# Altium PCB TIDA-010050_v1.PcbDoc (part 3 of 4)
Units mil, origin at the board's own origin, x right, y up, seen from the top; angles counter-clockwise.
Board outline 2060.77 x 1300 mil, 4 copper layers (Top Layer, signal1, signal2, Bottom Layer), stack 23.6 mil thick; 58 components, 30 nets, 158 pads, 41 vias.
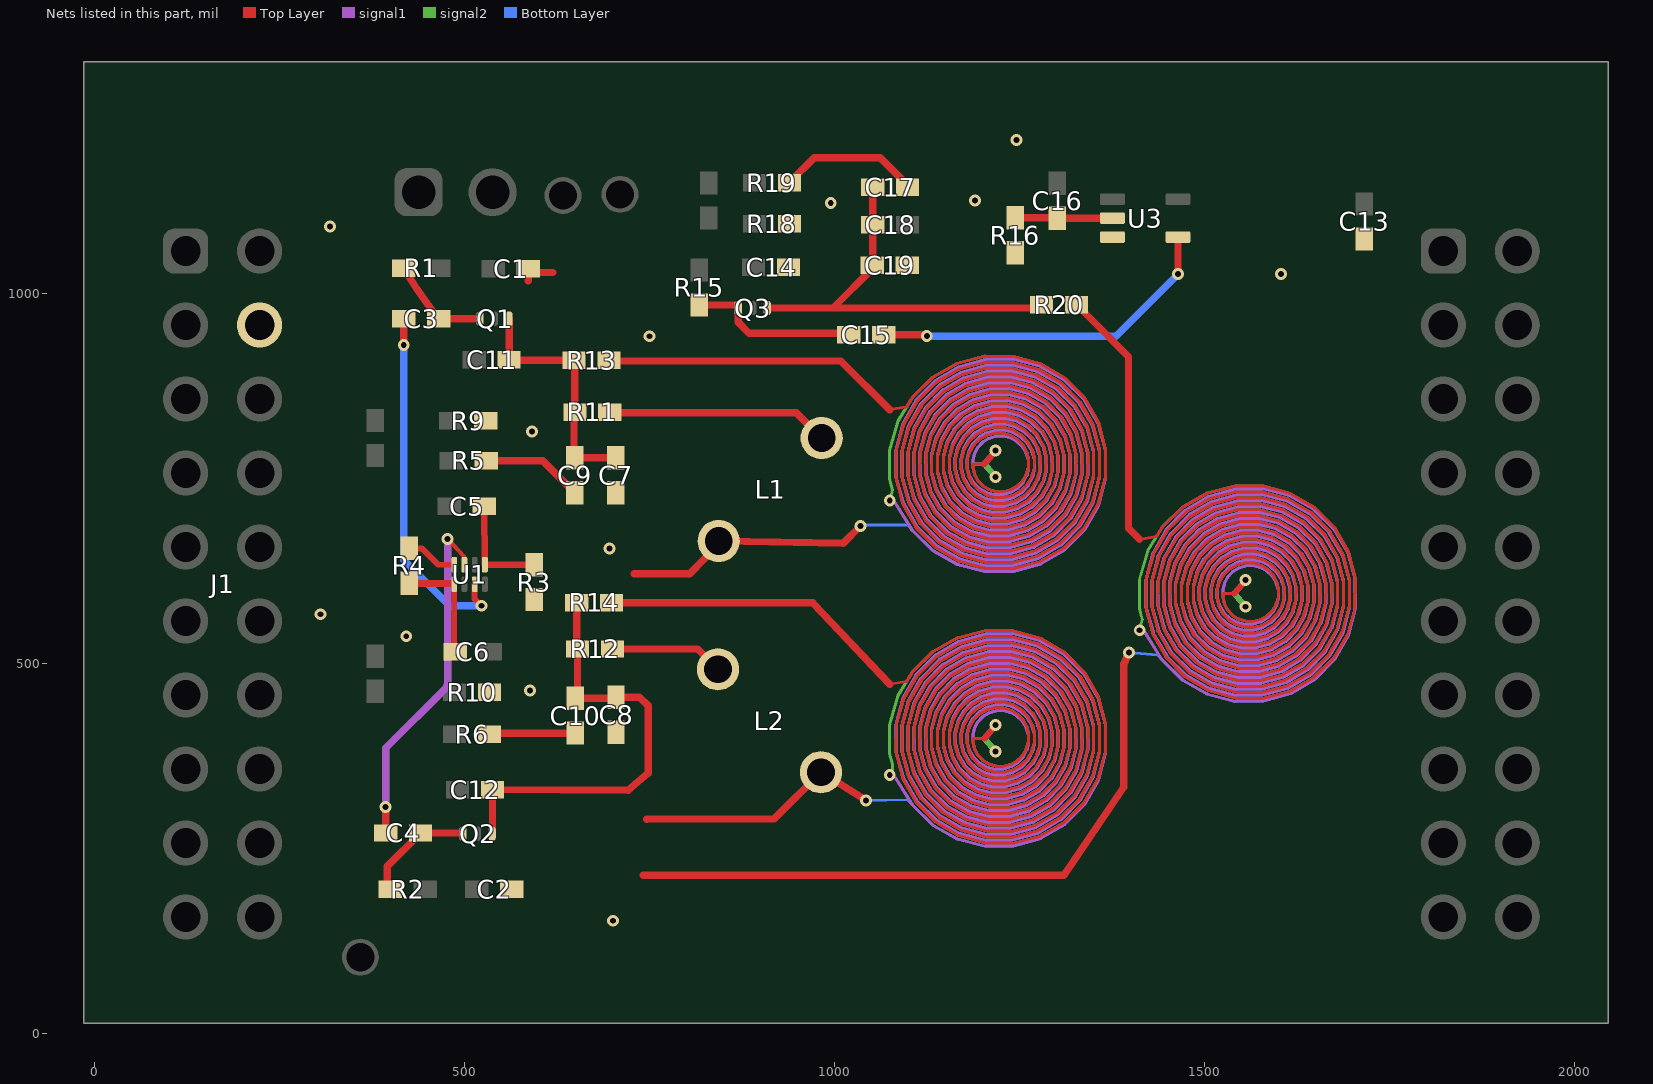
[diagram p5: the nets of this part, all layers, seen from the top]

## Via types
v1: diameter 16, hole 8, Top Layer to Bottom Layer, 40 vias
v2: diameter 16/16/16/16 (per signal layer), hole 8, Top Layer to Bottom Layer, 1 vias

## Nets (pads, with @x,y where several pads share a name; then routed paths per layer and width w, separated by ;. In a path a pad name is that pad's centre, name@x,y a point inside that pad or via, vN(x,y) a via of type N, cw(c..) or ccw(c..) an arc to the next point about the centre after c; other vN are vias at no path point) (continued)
GND: (continued)
  Bottom Layer w4: v1@1035.99,686.52 1098.94,686.52 1105.24,679.29 1132.74,652.26 1166.23,633.31 1203.39,623.7 1241.69,624.03 1278.51,634.24 1311.36,653.59 1338.02,680.72 1356.71,713.76 1366.19,750.41 1365.85,788.18 1355.78,824.5 1336.69,856.89 1309.93,883.18 1277.36,901.6 1241.21,910.94 1203.96,910.61 1168.16,900.67 1136.22,881.85 1110.3,855.46 1092.15,823.34 1082.94,787.7 1083.27,750.98 1093.08,715.69 1111.64,684.2 1137.65,658.66 1169.31,640.77 1204.45,631.7 1240.64,632.03 1275.43,641.7 1306.45,660 1331.62,685.64 1349.25,716.84 1358.19,751.47 1357.85,787.13 1348.32,821.41 1330.29,851.98 1305.02,876.78 1274.27,894.15 1240.16,902.94 1205.02,902.61 1171.24,893.22 1141.13,875.45 1116.71,850.55 1099.6,820.25 1090.94,786.65 1091.27,752.04 1100.53,718.77 1118.04,689.12 1142.56,665.06 1172.4,648.22 1205.5,639.7 1239.58,640.03 1272.34,649.15 1301.54,666.4 1325.22,690.55 1341.8,719.93 1350.19,752.52 1349.85,786.08 1340.87,818.32 1323.89,847.07 1300.11,870.38 1271.18,886.69 1239.1,894.94 1206.07,894.61 1174.33,885.76 1146.04,869.04 1123.11,845.64 1107.05,817.17 1098.94,785.6 1099.27,753.09 1107.99,721.86 1124.44,694.03 1147.48,671.46 1175.49,655.68 1206.55,647.7 1238.53,648.03 1269.25,656.61 1296.63,672.8 1318.82,695.46 1334.34,723.02 1342.19,753.57 1341.85,785.03 1333.41,815.24 1317.49,842.16 1295.19,863.98 1268.09,879.24 1238.05,886.94 1207.12,886.61 1177.42,878.31 1150.96,862.64 1129.51,840.72 1114.51,814.08 1106.94,784.54 1107.27,754.14 1115.44,724.95 1130.84,698.94 1152.39,677.87 1178.58,663.13 1207.6,655.7 1237.48,656.03 1266.16,664.06 1291.72,679.2 1312.42,700.37 1326.89,726.11 1334.19,754.63 1333.85,783.97 1325.96,812.15 1311.08,837.24 1290.28,857.57 1265.01,871.78 1237,878.94 1208.18,878.61 1180.51,870.85 1155.87,856.24 1135.91,835.81 1121.96,810.99 1114.94,783.49 1115.27,755.2 1122.9,728.04 1137.24,703.85 1157.3,684.27 1181.67,670.59 1208.66,663.7 1236.43,664.03 1263.08,671.52 1286.8,685.6 1306.02,705.29 1319.44,729.2 1326.19,755.68 1325.85,782.92 1318.5,809.06 1304.68,832.33 1285.37,851.17 1261.92,864.33 1235.94,870.94 1209.23,870.61 1183.6,863.4 1160.78,849.84 1142.31,830.9 1129.42,807.9 1122.94,782.44 1123.27,756.25 1130.35,731.12 1143.65,708.76 1162.21,690.67 1184.75,678.04 1209.71,671.7 1235.37,672.03 1259.99,678.97 1281.89,692 1299.61,710.2 1311.98,732.28 1318.19,756.73 1317.85,781.87 1311.05,805.97 1298.28,827.42 1280.46,844.77 1258.83,856.87 1234.89,862.94 1210.28,862.61 1186.68,855.94 1165.69,843.44 1148.71,825.99 1136.87,804.81 1130.94,781.38 1131.27,757.3 1137.81,734.21 1150.05,713.68 1167.12,697.07 1187.84,685.49 1210.76,679.7 1234.32,680.03 1256.9,686.43 1276.98,698.4 1293.21,715.11 1304.53,735.37 1310.19,757.78 1309.85,780.81 1303.59,802.88 1291.88,822.51 1275.55,838.37 1255.74,849.42 1233.84,854.94 1211.34,854.61 1189.77,848.49 1170.6,837.04 1155.12,821.08 1144.33,801.73 1138.94,780.33 1139.27,758.36 1145.26,737.3 1156.45,718.59 1172.04,703.47 1190.93,692.95 1211.82,687.7 1233.27,688.03 1253.81,693.88 1272.07,704.81 1286.81,720.02 1297.07,738.46 1302.19,758.84 1301.85,779.76 1296.14,799.8 1285.48,817.6 1270.63,831.97 1252.65,841.96 1232.78,846.94 1212.39,846.61 1192.86,841.03 1175.52,830.63 1161.52,816.16 1151.78,798.64 1146.94,779.28 1147.27,759.41 1152.72,740.39 1162.85,723.5 1176.95,709.87 1194.02,700.4 1212.87,695.7 1232.21,696.03 1250.72,701.34 1267.15,711.21 1280.41,724.93 1289.62,741.55 1294.19,759.89 1293.85,778.71 1288.68,796.71 1279.08,812.68 1265.72,825.57 1249.57,834.51 1231.73,838.94 1213.44,838.61 1195.95,833.58 1180.43,824.23 1167.92,811.25 1159.24,795.55 1154.94,778.22 1155.27,760.46 1160.17,743.48 1169.25,728.41 1181.86,716.28 1197.11,707.86 1213.92,703.7 1231.16,704.03 1247.64,708.79 1262.24,717.61 1274.01,729.85 1282.16,744.63 1286.19,760.94 1285.85,777.65 1281.23,793.62 1272.67,807.77 1260.81,819.16 1246.48,827.05 1230.68,830.94 1214.49,830.61 1199.04,826.12 1185.34,817.83 1174.32,806.34 1166.69,792.46 1162.94,777.17 1163.27,761.51 1167.63,746.56 1175.65,733.33 1186.77,722.68 1200.19,715.31 1214.98,711.7 1230.11,712.03 1244.55,716.25 1257.33,724.01 1267.61,734.76 1274.71,747.72 1278.19,762 1277.85,776.6 1273.77,790.53 1266.27,802.86 1255.9,812.76 1243.39,819.6 1229.62,822.94 1215.55,822.61 1202.12,818.67 1190.25,811.43 1180.72,801.43 1174.15,789.37 1170.94,776.12 1171.27,762.57 1175.08,749.65 1182.06,738.24 1191.69,729.08 1203.28,722.77 1216.03,719.7 1229.05,720.03 1241.46,723.7 1252.42,730.41 1261.2,739.67 1267.25,750.81 1270.19,763.05 1269.85,775.55 1266.32,787.45 1259.87,797.95 1250.99,806.36 1240.3,812.14 1228.57,814.94 1216.6,814.61 1205.21,811.21 1195.16,805.03 1187.12,796.51 1181.6,786.29 1178.94,775.06 1179.27,763.62 1182.53,752.74 1188.46,743.15 1196.6,735.48 1206.37,730.22 1217.08,727.7 1228,728.03 1238.37,731.16 1247.51,736.81 1254.8,744.58 1259.8,753.9 1262.19,764.1 1261.85,774.49 1258.86,784.36 1253.47,793.04 1246.07,799.96 1237.21,804.69 1227.52,806.94 1217.65,806.61 1208.3,803.76 1200.08,798.63 1193.52,791.6 1189.06,783.2 1186.94,774.01 1187.27,769.32 1202.52,769.32 ; v1(1042.51,314.54) 1098.94,315.41 1105.24,308.18 1132.74,281.15 1166.23,262.2 1203.4,252.59 1241.69,252.92 1278.52,263.13 1311.37,282.48 1338.03,309.61 1356.71,342.64 1366.19,379.3 1365.86,417.07 1355.78,453.39 1336.69,485.78 1309.93,512.07 1277.36,530.49 1241.21,539.83 1203.97,539.5 1168.16,529.56 1136.22,510.73 1110.31,484.35 1092.15,452.23 1082.94,416.59 1083.28,379.87 1093.08,344.57 1111.64,313.09 1137.66,287.55 1169.32,269.65 1204.45,260.59 1240.64,260.92 1275.43,270.59 1306.46,288.88 1331.63,314.52 1349.26,345.73 1358.19,380.35 1357.86,416.02 1348.33,450.3 1330.29,480.87 1305.02,505.67 1274.27,523.04 1240.16,531.83 1205.02,531.5 1171.25,522.1 1141.13,504.33 1116.71,479.44 1099.6,449.14 1090.94,415.54 1091.28,380.92 1100.54,347.66 1118.04,318 1142.57,293.95 1172.41,277.11 1205.5,268.59 1239.59,268.92 1272.34,278.04 1301.54,295.28 1325.22,319.44 1341.8,348.82 1350.19,381.41 1349.86,414.97 1340.87,447.21 1323.89,475.96 1300.11,499.26 1271.18,515.58 1239.11,523.83 1206.07,523.5 1174.34,514.65 1146.05,497.93 1123.11,474.52 1107.06,446.05 1098.94,414.48 1099.28,381.98 1107.99,350.75 1124.44,322.92 1147.48,300.35 1175.49,284.56 1206.56,276.59 1238.54,276.92 1269.25,285.49 1296.63,301.69 1318.82,324.35 1334.35,351.91 1342.19,382.46 1341.86,413.91 1333.42,444.12 1317.49,471.04 1295.2,492.86 1268.1,508.13 1238.05,515.83 1207.13,515.5 1177.42,507.19 1150.96,491.53 1129.51,469.61 1114.51,442.97 1106.94,413.43 1107.28,383.03 1115.44,353.84 1130.85,327.83 1152.39,306.75 1178.58,292.02 1207.61,284.59 1237.48,284.92 1266.17,292.95 1291.72,308.09 1312.42,329.26 1326.89,354.99 1334.19,383.51 1333.86,412.86 1325.96,441.04 1311.09,466.13 1290.29,486.46 1265.01,500.67 1237,507.83 1208.18,507.5 1180.51,499.74 1155.87,485.13 1135.91,464.7 1121.97,439.88 1114.94,412.38 1115.28,384.08 1122.9,356.92 1137.25,332.74 1157.3,313.16 1181.67,299.47 1208.66,292.59 1236.43,292.92 1263.08,300.4 1286.81,314.49 1306.02,334.17 1319.44,358.08 1326.19,384.57 1325.86,411.81 1318.51,437.95 1304.69,461.22 1285.37,480.06 1261.92,493.22 1235.95,499.83 1209.23,499.5 1183.6,492.28 1160.78,478.73 1142.32,459.79 1129.42,436.79 1122.94,411.32 1123.28,385.14 1130.35,360.01 1143.65,337.65 1162.22,319.56 1184.76,306.93 1209.71,300.59 1235.38,300.92 1259.99,307.86 1281.89,320.89 1299.62,339.09 1311.98,361.17 1318.19,385.62 1317.86,410.75 1311.05,434.86 1298.28,456.31 1280.46,473.66 1258.83,485.76 1234.89,491.83 1210.29,491.5 1186.69,484.83 1165.7,472.32 1148.72,454.88 1136.88,433.7 1130.94,410.27 1131.28,386.19 1137.81,363.1 1150.05,342.56 1167.13,325.96 1187.85,314.38 1210.77,308.59 1234.32,308.92 1256.9,315.31 1276.98,327.29 1293.22,344 1304.53,364.26 1310.19,386.67 1309.86,409.7 1303.6,431.77 1291.88,451.4 1275.55,467.26 1255.74,478.31 1233.84,483.83 1211.34,483.5 1189.78,477.37 1170.61,465.92 1155.12,449.96 1144.33,430.61 1138.94,409.22 1139.28,387.24 1145.26,366.19 1156.45,347.48 1172.04,332.36 1190.93,321.84 1211.82,316.59 1233.27,316.92 1253.81,322.77 1272.07,333.69 1286.81,348.91 1297.07,367.35 1302.19,387.73 1301.86,408.65 1296.14,428.68 1285.48,446.48 1270.64,460.86 1252.66,470.85 1232.79,475.83 1212.39,475.5 1192.86,469.92 1175.52,459.52 1161.52,445.05 1151.79,427.53 1146.94,408.16 1147.28,388.3 1152.72,369.28 1162.85,352.39 1176.95,338.76 1194.02,329.29 1212.87,324.59 1232.22,324.92 1250.73,330.22 1267.16,340.1 1280.41,353.82 1289.62,370.43 1294.19,388.78 1293.86,407.59 1288.69,425.6 1279.08,441.57 1265.73,454.45 1249.57,463.4 1231.73,467.83 1213.44,467.5 1195.95,462.46 1180.43,453.12 1167.92,440.14 1159.24,424.44 1154.94,407.11 1155.28,389.35 1160.17,372.36 1169.26,357.3 1181.86,345.16 1197.11,336.75 1213.93,332.59 1231.16,332.92 1247.64,337.68 1262.25,346.5 1274.01,358.73 1282.16,373.52 1286.19,389.83 1285.86,406.54 1281.23,422.51 1272.68,436.66 1260.81,448.05 1246.48,455.94 1230.68,459.83 1214.5,459.5 1199.04,455.01 1185.34,446.72 1174.32,435.23 1166.7,421.35 1162.94,406.06 1163.28,390.4 1167.63,375.45 1175.66,362.21 1186.78,351.57 1200.2,344.2 1214.98,340.59 1230.11,340.92 1244.55,345.13 1257.33,352.9 1267.61,363.65 1274.71,376.61 1278.19,390.89 1277.86,405.49 1273.78,419.42 1266.28,431.75 1255.9,441.65 1243.39,448.49 1229.63,451.83 1215.55,451.5 1202.13,447.56 1190.26,440.32 1180.72,430.31 1174.15,418.26 1170.94,405 1171.28,391.46 1175.08,378.54 1182.06,367.12 1191.69,357.97 1203.28,351.66 1216.03,348.59 1229.06,348.92 1241.46,352.59 1252.42,359.3 1261.21,368.56 1267.25,379.7 1270.19,391.94 1269.86,404.43 1266.32,416.33 1259.87,426.84 1250.99,435.25 1240.31,441.03 1228.57,443.83 1216.6,443.5 1205.21,440.1 1195.17,433.92 1187.13,425.4 1181.61,415.17 1178.94,403.95 1179.28,392.51 1182.54,381.63 1188.46,372.04 1196.6,364.37 1206.37,359.11 1217.09,356.59 1228,356.92 1238.38,360.04 1247.51,365.7 1254.81,373.47 1259.8,382.79 1262.19,392.99 1261.86,403.38 1258.87,413.24 1253.47,421.92 1246.08,428.85 1237.22,433.58 1227.52,435.83 1217.66,435.5 1208.3,432.65 1200.08,427.51 1193.53,420.49 1189.06,412.09 1186.94,402.9 1187.28,398.21 1202.53,398.21 ; v1(1397.9,514.36) 1436.74,511.26 1443.03,504.03 1470.53,477 1504.02,458.05 1541.19,448.44 1579.49,448.77 1616.31,458.98 1649.16,478.33 1675.82,505.47 1694.5,538.5 1703.98,575.15 1703.65,612.93 1693.57,649.24 1674.48,681.63 1647.73,707.92 1615.15,726.34 1579,735.68 1541.76,735.35 1505.95,725.41 1474.01,706.59 1448.1,680.2 1429.94,648.08 1420.74,612.44 1421.07,575.72 1430.87,540.43 1449.43,508.95 1475.45,483.4 1507.11,465.51 1542.24,456.44 1578.43,456.77 1613.22,466.44 1644.25,484.74 1669.42,510.38 1687.05,541.58 1695.98,576.21 1695.65,611.87 1686.12,646.15 1668.08,676.72 1642.81,701.52 1612.06,718.89 1577.95,727.68 1542.81,727.35 1509.04,717.96 1478.93,700.19 1454.5,675.29 1437.39,644.99 1428.74,611.39 1429.07,576.78 1438.33,543.51 1455.83,513.86 1480.36,489.8 1510.2,472.96 1543.29,464.44 1577.38,464.77 1610.13,473.89 1639.33,491.14 1663.02,515.29 1679.59,544.67 1687.98,577.26 1687.65,610.82 1678.66,643.07 1661.68,671.81 1637.9,695.12 1608.98,711.43 1576.9,719.68 1543.86,719.35 1512.13,710.5 1483.84,693.78 1460.9,670.38 1444.85,641.91 1436.74,610.34 1437.07,577.83 1445.78,546.6 1462.24,518.77 1485.27,496.21 1513.28,480.42 1544.35,472.44 1576.33,472.77 1607.05,481.35 1634.42,497.54 1656.61,520.2 1672.14,547.76 1679.98,578.31 1679.65,609.77 1671.21,639.98 1655.28,666.9 1632.99,688.72 1605.89,703.98 1575.84,711.68 1544.92,711.35 1515.21,703.05 1488.75,687.38 1467.3,665.47 1452.3,638.82 1444.74,609.28 1445.07,578.88 1453.24,549.69 1468.64,523.68 1490.18,502.61 1516.37,487.87 1545.4,480.44 1575.27,480.77 1603.96,488.8 1629.51,503.94 1650.21,525.11 1664.68,550.85 1671.98,579.37 1671.65,608.71 1663.75,636.89 1648.88,661.99 1628.08,682.32 1602.8,696.52 1574.79,703.68 1545.97,703.35 1518.3,695.59 1493.66,680.98 1473.71,660.55 1459.76,635.73 1452.74,608.23 1453.07,579.94 1460.69,552.78 1475.04,528.59 1495.09,509.01 1519.46,495.33 1546.45,488.44 1574.22,488.77 1600.87,496.26 1624.6,510.34 1643.81,530.03 1657.23,553.94 1663.98,580.42 1663.65,607.66 1656.3,633.8 1642.48,657.07 1623.17,675.91 1599.71,689.07 1573.74,695.68 1547.02,695.35 1521.39,688.14 1498.57,674.58 1480.11,655.64 1467.21,632.64 1460.74,607.18 1461.07,580.99 1468.15,555.87 1481.44,533.51 1500.01,515.41 1522.55,502.78 1547.51,496.44 1573.17,496.77 1597.78,503.71 1619.69,516.74 1637.41,534.94 1649.78,557.02 1655.98,581.47 1655.65,606.61 1648.84,630.71 1636.08,652.16 1618.25,669.51 1596.62,681.61 1572.68,687.68 1548.08,687.35 1524.48,680.68 1503.49,668.18 1486.51,650.73 1474.67,629.56 1468.74,606.12 1469.07,582.04 1475.6,558.95 1487.84,538.42 1504.92,521.81 1525.64,510.24 1548.56,504.44 1572.11,504.77 1594.69,511.17 1614.77,523.15 1631.01,539.85 1642.32,560.11 1647.98,582.53 1647.65,605.55 1641.39,627.63 1629.67,647.25 1613.34,663.11 1593.54,674.16 1571.63,679.68 1549.13,679.35 1527.57,673.23 1508.4,661.78 1492.91,645.82 1482.12,626.47 1476.74,605.07 1477.07,583.1 1483.06,562.04 1494.24,543.33 1509.83,528.21 1528.72,517.69 1549.61,512.44 1571.06,512.77 1591.61,518.62 1609.86,529.55 1624.61,544.76 1634.87,563.2 1639.98,583.58 1639.65,604.5 1633.93,624.54 1623.27,642.34 1608.43,656.71 1590.45,666.71 1570.58,671.68 1550.18,671.35 1530.65,665.77 1513.31,655.38 1499.31,640.9 1489.58,623.38 1484.74,604.02 1485.07,584.15 1490.51,565.13 1500.65,548.24 1514.74,534.62 1531.81,525.15 1550.67,520.44 1570.01,520.77 1588.52,526.08 1604.95,535.95 1618.2,549.68 1627.41,566.29 1631.98,584.63 1631.65,603.45 1626.48,621.45 1616.87,637.43 1603.52,650.31 1587.36,659.25 1569.52,663.68 1551.24,663.35 1533.74,658.32 1518.22,648.97 1505.71,635.99 1497.03,620.29 1492.74,602.96 1493.07,585.2 1497.97,568.22 1507.05,553.15 1519.66,541.02 1534.9,532.6 1551.72,528.44 1568.95,528.77 1585.43,533.53 1600.04,542.35 1611.8,554.59 1619.96,569.38 1623.98,585.69 1623.65,602.39 1619.02,618.36 1610.47,632.51 1598.6,643.91 1584.27,651.8 1568.47,655.68 1552.29,655.35 1536.83,650.86 1523.14,642.57 1512.11,631.08 1504.49,617.2 1500.74,601.91 1501.07,586.26 1505.42,571.31 1513.45,558.07 1524.57,547.42 1537.99,540.06 1552.77,536.44 1567.9,536.77 1582.34,540.99 1595.13,548.75 1605.4,559.5 1612.5,572.46 1615.98,586.74 1615.65,601.34 1611.57,615.27 1604.07,627.6 1593.69,637.5 1581.18,644.34 1567.42,647.68 1553.34,647.35 1539.92,643.41 1528.05,636.17 1518.52,626.17 1511.94,614.12 1508.74,600.86 1509.07,587.31 1512.87,574.39 1519.85,562.98 1529.48,553.82 1541.08,547.51 1553.83,544.44 1566.85,544.77 1579.25,548.44 1590.21,555.15 1599,564.41 1605.05,575.55 1607.98,587.79 1607.65,600.29 1604.11,612.19 1597.67,622.69 1588.78,631.1 1578.1,636.89 1566.36,639.68 1554.4,639.35 1543.01,635.95 1532.96,629.77 1524.92,621.26 1519.4,611.03 1516.74,599.8 1517.07,588.36 1520.33,577.48 1526.25,567.89 1534.39,560.22 1544.16,554.97 1554.88,552.44 1565.79,552.77 1576.17,555.9 1585.3,561.56 1592.6,569.32 1597.59,578.64 1599.98,588.85 1599.65,599.23 1596.66,609.1 1591.26,617.78 1583.87,624.7 1575.01,629.43 1565.31,631.68 1555.45,631.35 1546.09,628.5 1537.87,623.37 1531.32,616.34 1526.85,607.94 1524.74,598.75 1525.07,594.06 1540.32,594.06
  Bottom Layer w8: 1202.52,769.32 1217.55,751.58 v1@1217.77,751.32 ; 1202.53,398.21 1217.56,380.47 v1@1217.78,380.21 ; 1540.32,594.06 v1(1555.28,576.26) v1@1555.57,576.06
  other v1: 700.67,151.81 1217.49,380.41 1217.49,416.41 588.08,462.89 421,536.41 305,566.09 1555.28,612.26 695.87,654.94 1217.48,751.52 1217.48,787.52 590.97,813 750,941.87 1603.2,1026.19 318,1090.29 994.77,1122 1189.6,1125.54 1246,1207
NetC3_1: C3.1 U1.7 | length 489.7
  Top Layer w8: U1.7@513.49,606.59 513.49,586.78 v1(522.69,577.58)
  Top Layer w10: v2@417.66,933 C3.1@417.66,965.7
  Bottom Layer w10: v2@417.66,933 417.66,639.45 479.53,577.58 v1(522.69,577.58)
  other v2: 417.66,930
NetC3_2: C3.2 Q1.1@520.61,965.63 R1.1 | length 137.3
  Top Layer w10: R1.1@417.68,1033.56 434.12,1007.67 C3.2@464.18,965.7 ; C3.2@464.91,965.7 512.87,965.7 ; 512.55,965.91 Q1.1@519.63,965.63
NetC4_1: C4.1 U1.3 | length 476.1
  Top Layer w6: v1(476.91,667.92) 499.71,643.53 U1.3@499.71,632.97
  Top Layer w10: C4.1@393.14,270.45 v1(393.14,305.74)
  signal1 w10: v1(393.14,305.74) 393.14,385.28 476.91,469.05 v1(476.91,667.92)
NetC4_2: C4.2 Q2.1@497.7,269.45 R2.1 | length 151.2
  Top Layer w10: R2.1@395.47,194.14 395.47,225.54 C4.2@440.38,270.45 Q2.1@496.7,270.45
NetC5_2: C5.2 R3.2 U1.1 | length 146
  Top Layer w9: C5.2@526.29,712.21 U1.1@527.27,632.97 R3.2@593.67,632.97
  Top Layer w10: R3.2@593.67,632.97 R3.2@593.91,633.21
NetC6_2: C6.2 R4.2 U1.5 | length 152
  Top Layer w8: C6.2@485.93,514.36 U1.5@485.93,606.59
  Top Layer w10: R4.2@425.05,607.96 U1.5@484.76,607.6
NetC7_1: C7.1 C9.2 C11.1 Q1.3@559.98,965.63 R11.2 R13.2 | length 324.2
  Top Layer w10: C11.1@559.98,910.31 Q1.3@559.98,965.63 ; C11.1@570.91,909.21 R13.2@647.82,909.21 648.63,908.4 648.63,848.07 647.75,847.19 647.75,778.87 C9.2@648.99,777.62 707.63,777.62 C7.1@707.99,777.26
NetC8_1: C8.1 C10.2 C12.1 Q2.3@537.07,269.45 R12.2 R14.2 | length 599.6
  Top Layer w10: Q2.3@537.07,269.45 537.6,269.98 C12.1@537.6,329.21 720.91,328.21 747.91,351.21 747.91,442.21 736.34,453.78 C8.1@704.53,453.78 703.53,452.78 C10.2@649.53,452.78 652.53,455.78 R12.2@652.53,519.16 651.28,520.4 R14.2@651.28,577.28
NetC9_1: C9.1 R5.1 | length 137.9
  Top Layer w10: R5.1@529.03,773.64 605.73,773.64 C9.1@648.99,730.38
NetC10_1: C10.1 R6.1 | length 116.6
  Top Layer w10: R6.1@533.53,404.19 534.87,405.53 C10.1@649.53,405.53
NetC15_1: C15.1 U3.4 | length 483.3
  Top Layer w10: C15.1@1066.4,944.05 1122.54,944.05 v1(1124.59,942) ; v1(1464.08,1025.8) U3.4@1464.08,1075.83
  Bottom Layer w10: v1(1124.59,942) 1380.28,942 v1(1464.08,1025.8)
NetC15_2: C15.2 Q3.1@869.65,980 R15.1 | length 228.3
  Top Layer w10: R15.1@816.95,984.05 865.6,984.05 Q3.1@869.65,980 869.65,960.67 884.31,946 1013.97,946 C15.2@1016.97,943
NetC16_2: C16.2 R16.2 U3.2 | length 132.4
  Top Layer w10: R16.2@1245,1101.42 R16.2@1244.32,1102.1 1300.35,1102.1 C16.2@1301.03,1101.42 U3.2@1375.5,1101.42
NetC17_1: C17.1 R19.1 | length 187.6
  Top Layer w10: R19.1@940.24,1151 972.62,1183.38 1061.62,1183.38 C17.1@1099,1146
NetC17_2: C17.2 C18.1 C19.1 Q3.3@909.02,980 R20.2 | length 561.4
  Top Layer w10: Q3.3@909.02,980 997.82,980 ; C17.2@1053.85,1145.5 C17.2@1051.38,1143.02 C18.1@1051.38,1092.5 1051.38,1033.56 997.82,980 ; R20.2@1279.7,984.74 1274.96,980 997.82,980
NetL1_2: L1.2 R11.1 | length 305.1
  Top Layer w8: L1.2@978.57,796.35 L1.2@982.52,800.29
  Top Layer w10: R11.1@697.25,838.62 948.2,838.62 L1.2@982.52,804.29
NetL2_2: L2.2 R12.1 | length 153.9
  Top Layer w10: R12.1@699.77,519.16 814.89,519.16 L2.2@842.33,491.72
pads on no net: J1.2 J1.5 J1.7 J1.9 J1.10 J1.13 J1.15 J1.16 J1.17 J1.18 J1.20 J2.1 J2.2 J2.3 J2.5 J2.6 J2.7 J2.8 J2.9 J2.10 J2.11 J2.12 J2.13 J2.14 J2.15 J2.16 J2.18 J2.20 Q1.1@519.63,965.63 Q1.2@540.3,965.63 Q1.3@560.97,965.63 Q2.1@496.71,269.45 Q2.2@517.38,269.45 Q2.3@538.05,269.45 Q3.1@868.66,980 Q3.2@889.33,980 Q3.3@910,980
copper on no net: | length 425141.8
  Top Layer w1: 6511.74,3202.74 9354.31,6045.31 ; 6511.74,3262.74 9294.31,6045.31 ; 6511.74,3322.74 9234.31,6045.31 ; 6511.74,3382.74 9174.31,6045.31 ; 6511.74,3442.74 9114.31,6045.31 ; 6511.74,3502.74 9054.31,6045.31 ; 6511.74,3562.74 8994.31,6045.31 ; 6511.74,3622.74 8934.31,6045.31 ; 6511.74,3682.74 8874.31,6045.31 ; 6511.74,3742.74 8814.31,6045.31 ; 6511.74,3802.74 8754.31,6045.31 ; 6511.74,3862.74 8694.31,6045.31 ; 6511.74,3922.74 8634.31,6045.31 ; 6511.74,3982.74 8574.31,6045.31 ; 6511.74,4042.74 8514.31,6045.31 ; 6511.74,4102.74 8454.31,6045.31 ; 6511.74,4162.74 8394.31,6045.31 ; 6511.74,4222.74 8334.31,6045.31 ; 6511.74,4282.74 8274.31,6045.31 ; 6511.74,4342.74 8214.31,6045.31 ; 6511.74,4402.74 8154.31,6045.31 ; 6511.74,4462.74 8094.31,6045.31 ; 6511.74,4522.74 8034.31,6045.31 ; 6511.74,4582.74 7974.31,6045.31 ; 6511.74,4642.74 7914.31,6045.31 ; 6511.74,4702.74 7854.31,6045.31 ; 6511.74,4762.74 7794.31,6045.31 ; 6511.74,4822.74 7734.31,6045.31 ; 6511.74,4882.74 7674.31,6045.31 ; 6511.74,4942.74 7614.31,6045.31 ; 6511.74,5002.74 7554.31,6045.31 ; 6511.74,5062.74 7494.31,6045.31 ; 6511.74,5122.74 7434.31,6045.31 ; 6511.74,5182.74 7374.31,6045.31 ; 6511.74,5242.74 7314.31,6045.31 ; 6511.74,5302.74 7254.31,6045.31 ; 6511.74,5362.74 7194.31,6045.31 ; 6511.74,5422.74 7134.31,6045.31 ; 6511.74,5482.74 7074.31,6045.31 ; 6511.74,5542.74 7014.31,6045.31 ; 6511.74,5602.74 6954.31,6045.31 ; 6511.74,5662.74 6894.31,6045.31 ; 6511.74,5722.74 6834.31,6045.31 ; 6511.74,5782.74 6774.31,6045.31 ; 6511.74,5842.74 6714.31,6045.31 ; 6511.74,5902.74 6654.31,6045.31 ; 6511.74,5962.74 6594.31,6045.31 ; 6511.74,6022.74 6534.31,6045.31 ; 6550,3181 9414.31,6045.31 ; 6610,3181 9474.31,6045.31 ; 6670,3181 9534.31,6045.31 ; 6730,3181 9594.31,6045.31 ; 6790,3181 9654.31,6045.31 ; 6850,3181 9714.31,6045.31 ; 6910,3181 9774.31,6045.31 ; 6970,3181 9834.31,6045.31 ; 7030,3181 9894.31,6045.31 ; 7090,3181 9954.31,6045.31 ; 7150,3181 10014.31,6045.31 ; 7210,3181 10074.31,6045.31 ; 7270,3181 10134.31,6045.31 ; 7330,3181 10194.31,6045.31 ; 7390,3181 10254.31,6045.31 ; 7450,3181 10314.31,6045.31 ; 7510,3181 10374.31,6045.31 ; 7570,3181 10434.31,6045.31 ; 7630,3181 10494.31,6045.31 ; 7690,3181 10554.31,6045.31 ; 7750,3181 10614.31,6045.31 ; 7810,3181 10674.31,6045.31 ; 7870,3181 10734.31,6045.31 ; 7930,3181 10794.31,6045.31 ; 7990,3181 10854.31,6045.31 ; 8050,3181 10914.31,6045.31 ; 8110,3181 10974.31,6045.31 ; 8170,3181 11034.31,6045.31 ; 8230,3181 11050.54,6001.54 ; 8290,3181 11050.54,5941.54 ; 8350,3181 11050.54,5881.54 ; 8410,3181 11050.54,5821.54 ; 8470,3181 11050.54,5761.54 ; 8530,3181 11050.54,5701.54 ; 8590,3181 11050.54,5641.54 ; 8650,3181 11050.54,5581.54 ; 8710,3181 11050.54,5521.54 ; 8770,3181 11050.54,5461.54 ; 8830,3181 11050.54,5401.54 ; 8890,3181 11050.54,5341.54 ; 8950,3181 11050.54,5281.54 ; 9010,3181 11050.54,5221.54 ; 9070,3181 11050.54,5161.54 ; 9130,3181 11050.54,5101.54 ; 9190,3181 11050.54,5041.54 ; 9250,3181 11050.54,4981.54 ; 9310,3181 11050.54,4921.54 ; 9370,3181 11050.54,4861.54 ; 9430,3181 11050.54,4801.54 ; 9490,3181 11050.54,4741.54 ; 9550,3181 11050.54,4681.54 ; 9610,3181 11050.54,4621.54 ; 9670,3181 11050.54,4561.54 ; 9730,3181 11050.54,4501.54 ; 9790,3181 11050.54,4441.54 ; 9850,3181 11050.54,4381.54 ; 9910,3181 11050.54,4321.54 ; 9930.86,6095.08 10030.54,6194.77 10150.54,6314.77 10270.54,6434.77 10390.54,6554.77 10510.54,6674.77 10630.54,6794.77 10750.54,6914.77 10870.54,7034.77 10990.54,7154.77 11050.54,7214.77 ; 9930.86,6155.08 9970.54,6194.77 10090.54,6314.77 10210.54,6434.77 10330.54,6554.77 10450.54,6674.77 10570.54,6794.77 10690.54,6914.77 10810.54,7034.77 10930.54,7154.77 11050.54,7274.77 ; 9930.86,6215.08 10030.54,6314.77 10150.54,6434.77 10270.54,6554.77 10390.54,6674.77 10510.54,6794.77 10630.54,6914.77 10750.54,7034.77 10870.54,7154.77 10990.54,7274.77 11050.54,7334.77 ; 9930.86,6275.08 9970.54,6314.77 10090.54,6434.77 10210.54,6554.77 10330.54,6674.77 10450.54,6794.77 10570.54,6914.77 10690.54,7034.77 10810.54,7154.77 10930.54,7274.77 11050.54,7394.77 ; 9930.86,6335.08 10030.54,6434.77 10150.54,6554.77 10270.54,6674.77 10390.54,6794.77 10510.54,6914.77 10630.54,7034.77 10750.54,7154.77 10870.54,7274.77 10990.54,7394.77 ; 9930.86,6395.08 9970.54,6434.77 10090.54,6554.77 10210.54,6674.77 10330.54,6794.77 10450.54,6914.77 10570.54,7034.77 10690.54,7154.77 10810.54,7274.77 10930.54,7394.77 ; 9930.86,6455.08 10030.54,6554.77 10150.54,6674.77 10270.54,6794.77 10390.54,6914.77 10510.54,7034.77 10630.54,7154.77 10750.54,7274.77 10870.54,7394.77 ; 9930.86,6515.08 9970.54,6554.77 10090.54,6674.77 10210.54,6794.77 10330.54,6914.77 10450.54,7034.77 10570.54,7154.77 10690.54,7274.77 10810.54,7394.77 ; 9930.86,6575.08 10030.54,6674.77 10150.54,6794.77 10270.54,6914.77 10390.54,7034.77 10510.54,7154.77 10630.54,7274.77 10750.54,7394.77 ; 9930.86,6635.08 9970.54,6674.77 10090.54,6794.77 10210.54,6914.77 10330.54,7034.77 10450.54,7154.77 10570.54,7274.77 10690.54,7394.77 ; 9930.86,6695.08 10030.54,6794.77 10150.54,6914.77 10270.54,7034.77 10390.54,7154.77 10510.54,7274.77 10630.54,7394.77 ; 9930.86,6755.08 9970.54,6794.77 10090.54,6914.77 10210.54,7034.77 10330.54,7154.77 10450.54,7274.77 10570.54,7394.77 ; 9930.86,6815.08 10030.54,6914.77 10150.54,7034.77 10270.54,7154.77 10390.54,7274.77 10510.54,7394.77 ; 9930.86,6875.08 9970.54,6914.77 10090.54,7034.77 10210.54,7154.77 10330.54,7274.77 10450.54,7394.77 ; 9930.86,6935.08 10030.54,7034.77 10150.54,7154.77 10270.54,7274.77 10390.54,7394.77 ; 9930.86,6995.08 9970.54,7034.77 10090.54,7154.77 10210.54,7274.77 10330.54,7394.77 ; 9930.86,7055.08 10030.54,7154.77 10150.54,7274.77 10270.54,7394.77 ; 9930.86,7115.08 9970.54,7154.77 10090.54,7274.77 10210.54,7394.77 ; 9930.86,7175.08 10030.54,7274.77 10150.54,7394.77 ; 9930.86,7235.08 9970.54,7274.77 10090.54,7394.77 ; 9930.86,7295.08 10030.54,7394.77 ; 9930.86,7355.08 9970.54,7394.77 ; 9970,3181 11050.54,4261.54 ; 9970.54,6074.77 10090.54,6194.77 10210.54,6314.77 10330.54,6434.77 10450.54,6554.77 10570.54,6674.77 10690.54,6794.77 10810.54,6914.77 10930.54,7034.77 11050.54,7154.77 ; 10030,3181 11050.54,4201.54 ; 10030.54,6074.77 10150.54,6194.77 10270.54,6314.77 10390.54,6434.77 10510.54,6554.77 10630.54,6674.77 10750.54,6794.77 10870.54,6914.77 10990.54,7034.77 11050.54,7094.77 ; 10090,3181 11050.54,4141.54 ; 10090.54,6074.77 10210.54,6194.77 10330.54,6314.77 10450.54,6434.77 10570.54,6554.77 10690.54,6674.77 10810.54,6794.77 10930.54,6914.77 11050.54,7034.77 ; 10150,3181 11050.54,4081.54 ; 10150.54,6074.77 10270.54,6194.77 10390.54,6314.77 10510.54,6434.77 10630.54,6554.77 10750.54,6674.77 10870.54,6794.77 10990.54,6914.77 11050.54,6974.77 ; 10210,3181 11050.54,4021.54 ; 10210.54,6074.77 10330.54,6194.77 10450.54,6314.77 10570.54,6434.77 10690.54,6554.77 10810.54,6674.77 10930.54,6794.77 11050.54,6914.77 ; 10270,3181 11050.54,3961.54 ; 10270.54,6074.77 10390.54,6194.77 10510.54,6314.77 10630.54,6434.77 10750.54,6554.77 10870.54,6674.77 10990.54,6794.77 11050.54,6854.77 ; 10330,3181 11050.54,3901.54 ; 10330.54,6074.77 10450.54,6194.77 10570.54,6314.77 10690.54,6434.77 10810.54,6554.77 10930.54,6674.77 11050.54,6794.77 ; 10390,3181 11050.54,3841.54 ; 10390.54,6074.77 10510.54,6194.77 10630.54,6314.77 10750.54,6434.77 10870.54,6554.77 10990.54,6674.77 11050.54,6734.77 ; 10450,3181 11050.54,3781.54 ; 10450.54,6074.77 10570.54,6194.77 10690.54,6314.77 10810.54,6434.77 10930.54,6554.77 11050.54,6674.77 ; 10510,3181 11050.54,3721.54 ; 10510.54,6074.77 10630.54,6194.77 10750.54,6314.77 10870.54,6434.77 10990.54,6554.77 11050.54,6614.77 ; 10570,3181 11050.54,3661.54 ; 10570.54,6074.77 10690.54,6194.77 10810.54,6314.77 10930.54,6434.77 11050.54,6554.77 ; 10630,3181 11050.54,3601.54 ; 10630.54,6074.77 10750.54,6194.77 10870.54,6314.77 10990.54,6434.77 11050.54,6494.77 ; 10690,3181 11050.54,3541.54 ; 10690.54,6074.77 10810.54,6194.77 10930.54,6314.77 11050.54,6434.77 ; 10750,3181 11050.54,3481.54 ; 10750.54,6074.77 10870.54,6194.77 10990.54,6314.77 11050.54,6374.77 ; 10810,3181 11050.54,3421.54 ; 10810.54,6074.77 10930.54,6194.77 11050.54,6314.77 ; 10870,3181 11050.54,3361.54 ; 10870.54,6074.77 10990.54,6194.77 11050.54,6254.77 ; 10930,3181 11050.54,3301.54 ; 10930.54,6074.77 11050.54,6194.77 ; 10990,3181 11050.54,3241.54 ; 10990.54,6074.77 11050.54,6134.77
  Top Layer w15: 6511.74,6194.77 6921.65,6194.77 7851.39,6194.77 8711.16,6194.77 9361,6194.77 9930.86,6194.77 11050.54,6194.77 ; 6511.74,6314.77 6921.65,6314.77 7851.39,6314.77 8711.16,6314.77 9361,6314.77 9930.86,6314.77 11050.54,6314.77 ; 6511.74,6434.77 6921.65,6434.77 7851.39,6434.77 8711.16,6434.77 9361,6434.77 9930.86,6434.77 11050.54,6434.77 ; 6511.74,6554.77 6921.65,6554.77 7851.39,6554.77 8711.16,6554.77 9361,6554.77 9930.86,6554.77 11050.54,6554.77 ; 6511.74,6674.77 6921.65,6674.77 7851.39,6674.77 8711.16,6674.77 9361,6674.77 9930.86,6674.77 11050.54,6674.77 ; 6511.74,6794.77 6921.65,6794.77 7851.39,6794.77 8711.16,6794.77 9361,6794.77 9930.86,6794.77 11050.54,6794.77 ; 6511.74,6914.77 6921.65,6914.77 7851.39,6914.77 8711.16,6914.77 9361,6914.77 9930.86,6914.77 11050.54,6914.77 ; 6511.74,7034.77 6921.65,7034.77 7851.39,7034.77 8711.16,7034.77 9361,7034.77 9930.86,7034.77 11050.54,7034.77 ; 6511.74,7154.77 6921.65,7154.77 7851.39,7154.77 8711.16,7154.77 9361,7154.77 9930.86,7154.77 11050.54,7154.77 ; 6511.74,7274.77 6921.65,7274.77 7851.39,7274.77 8711.16,7274.77 9361,7274.77 9930.86,7274.77 11050.54,7274.77 ; 6511.74,7394.77 11050.54,7394.77 ; 6921.65,7514.77 6921.65,6074.77 ; 7851.39,7514.77 7851.39,6074.77 ; 8711.16,7514.77 8711.16,6074.77 ; 9361,7514.77 9361,6074.77 ; 9930.86,7514.77 9930.86,6074.77 ; 6921.65,6074.77 7851.39,6074.77 ; 6921.65,6074.77 6511.74,6074.77 6511.74,7514.77 11050.54,7514.77 11050.54,6074.77 9930.86,6074.77 ; 7851.39,6074.77 8711.16,6074.77 ; 8711.16,6074.77 9361,6074.77 ; 9361,6074.77 9930.86,6074.77 ; 6511.74,3181.54 6511.74,6044.77 11050.54,6044.77 11050.54,3181.54 6511.74,3181.54

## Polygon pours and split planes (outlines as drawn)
GND on signal1 "SIGNAL1_GND_P048" (solid, remove dead copper, pour order 48): 47,1225 54,1225 1760.26,1225 1760.26,932.22 1751.22,932.22 782,932.22 782,48.82 780.56,50.25 25.57,50.25 25.57,1224.43
no net on signal1 "SIGNAL1_NONET_P012" (solid, remove dead copper, pour order 12): 333.98,91
no net on signal1 "SIGNAL1_NONET_P010" (solid, remove dead copper, pour order 10): 333.98,91
no net on signal1 "SIGNAL1_NONET_P000" (solid, remove dead copper, shelved, pour order 0): 589,1128 591,1126 690,1126 690,1053 696,1047 691,1042 577,1042 567.51,1051.49 567.51,1120 580,1120 588,1128
GND on Top Layer "TOP_LAYER_GND_P050" (solid, remove dead copper, pour order 50): 45.26,1224.58 52.26,1224.58 1760.26,1224.58 1760.26,954.58 1760.26,932.24 780.26,932.2 780.26,48.4 778.82,49.83 23.83,49.83 23.83,1224.01
GND on signal2 "SIGNAL2_GND_P052" (solid, remove dead copper, pour order 52): 46.7,1225.18 53.7,1225.18 1761.7,1225.18 1761.7,955.18 1761.7,932.24 1750.76,932.24 781.7,932.24 781.7,48.99 780.26,50.43 25.27,50.43 25.27,1224.6
GND on Bottom Layer "BOTTOM_LAYER_GND_P054" (solid, remove dead copper, pour order 54): 47.88,1224.24 54.88,1224.24 1762.88,1224.24 1762.88,954.24 1762.88,932.24 1752.88,932.24 782.88,932.24 782.88,48.05 781.45,49.49 26.46,49.49 26.46,1223.66

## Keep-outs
Keep-Out Layer:
  text ".Layer_Name" at 449,-564.49 h20

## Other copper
Top Layer:
  pour cut-out: 1332.98,963.18 cw(c1332.98,984.74) 1311.43,984.74 cw(c1332.98,984.74) 1332.98,1006.29 cw(c1332.98,984.74) 1354.54,984.74 cw(c1332.98,984.74)
  pour cut-out: 1066.69,769.32 ccw(c1220.44,769.32) 1220.44,615.56 ccw(c1220.44,769.32) 1374.2,769.32 ccw(c1220.44,769.32) 1220.44,923.08 ccw(c1220.44,769.32)
  pour cut-out: 1069.88,740.5 1083.98,696.72 1078.06,696.72 cw(c1074.25,718.66)
  pour cut-out: 1069.88,369.38 1083.99,325.61 1078.06,325.61 cw(c1074.26,347.55)
  pour cut-out: 1066.69,398.21 ccw(c1220.45,398.21) 1220.45,244.45 ccw(c1220.45,398.21) 1374.21,398.21 ccw(c1220.45,398.21) 1220.45,551.97 ccw(c1220.45,398.21)
  pour cut-out: 698.18,558.88 cw(c698.18,580.44) 676.62,580.44 cw(c698.18,580.44) 698.18,601.99 cw(c698.18,580.44) 719.73,580.44 cw(c698.18,580.44)
  pour cut-out: 695.87,886.84 cw(c695.87,908.4) 674.32,908.4 cw(c695.87,908.4) 695.87,929.95 cw(c695.87,908.4) 717.43,908.4 cw(c695.87,908.4)
  pour cut-out: 910.04,316.98 cw(c910.04,426.1) 802.02,410.61 cw(c918.12,410.61) 918.12,526.7 cw(c910.63,418.13) 1019.16,426.11 cw(c910.04,426.1)
  pour cut-out: 914.01,621.39 cw(c914.01,730.51) 804.89,730.51 cw(c914.01,730.51) 914.01,839.64 cw(c914.01,730.51) 1023.14,730.51 cw(c914.01,730.51)
  pour cut-out: 1392.44,895.54 1421.56,908.46 1339,989.97 1318.5,969.48 1400.54,887.44
  pour cut-out: 683.22,929.75 684.43,928.54 684.43,893.06 818.01,893.92 818.01,924.06 684.43,924.06
  pour cut-out: 712.72,598.69 713.93,597.48 713.93,562 816.95,562.66 816.95,593 713.93,593
  pour cut-out: 971.44,649.94
  text "Layer" at 6571.74,7424.77 h60
  text "Name" at 6981.65,7424.77 h60
  text "Material" at 7911.39,7424.77 h60
  text "Thickness" at 8771.16,7424.77 h60
  text "Constant" at 9421,7424.77 h60
  text "Board Layer Stack" at 9990.86,7424.77 h60
  text "1" at 6571.74,7304.77 h60
  text "Top Overlay" at 6981.65,7304.77 h60
  text "2" at 6571.74,7184.77 h60
  text "Top Solder" at 6981.65,7184.77 h60
  text "Solder Resist" at 7911.39,7184.77 h60
  text "0.40mil" at 8771.16,7184.77 h60
  text "3.5" at 9421,7184.77 h60
  text "3" at 6571.74,7064.77 h60
  text "Top Layer" at 6981.65,7064.77 h60
  text "Copper" at 7911.39,7064.77 h60
  text "1.40mil" at 8771.16,7064.77 h60
  text "4" at 6571.74,6944.77 h60
  text "Dielectric 1" at 6981.65,6944.77 h60
  text "FR-4" at 7911.39,6944.77 h60
  text "5.00mil" at 8771.16,6944.77 h60
  text "4.2" at 9421,6944.77 h60
  text "5" at 6571.74,6824.77 h60
  text "signal1" at 6981.65,6824.77 h60
  text "Copper" at 7911.39,6824.77 h60
  text "1.40mil" at 8771.16,6824.77 h60
  text "6" at 6571.74,6704.77 h60
  text "Dielectric 2" at 6981.65,6704.77 h60
  text "FR-4" at 7911.39,6704.77 h60
  text "8.00mil" at 8771.16,6704.77 h60
  text "4.2" at 9421,6704.77 h60
  text "7" at 6571.74,6584.77 h60
  text "signal2" at 6981.65,6584.77 h60
  text "Copper" at 7911.39,6584.77 h60
  text "1.40mil" at 8771.16,6584.77 h60
  text "8" at 6571.74,6464.77 h60
  text "Dielectric 3" at 6981.65,6464.77 h60
  text "FR-4" at 7911.39,6464.77 h60
  text "5.00mil" at 8771.16,6464.77 h60
  text "4.2" at 9421,6464.77 h60
  text "9" at 6571.74,6344.77 h60
  text "Bottom Layer" at 6981.65,6344.77 h60
  text "Copper" at 7911.39,6344.77 h60
  text "1.40mil" at 8771.16,6344.77 h60
  text "10" at 6571.74,6224.77 h60
  text "Bottom Solder" at 6981.65,6224.77 h60
  text "Solder Resist" at 7911.39,6224.77 h60
  text "0.40mil" at 8771.16,6224.77 h60
  text "3.5" at 9421,6224.77 h60
  text "11" at 6571.74,6104.77 h60
  text "Bottom Overlay" at 6981.65,6104.77 h60
  text ".Layer_Name" at 577,-858.49 h20
  text "F" at 1197.9,-137363.08 h20
  text "L" at 1249.3,-137363.08 h20
  text "O" at 1295.72,-137363.08 h20
  text "W" at 1362.03,-137363.08 h20
  text "_" at 1444.92,-137363.08 h20
  text "O" at 1491.34,-137363.08 h20
  text "U" at 1557.66,-137363.08 h20
  text "T" at 1619,-137363.08 h20
  text "1" at 1670.39,-137363.08 h20
Bottom Layer:
  text ".Layer_Name" at 577,-858.49 h20

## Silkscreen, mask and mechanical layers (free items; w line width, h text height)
Top Overlay:
  text "FLOW_VDD" at 494.63,1199 h20
  text "J2" at 1859,1144 h20
  text "J1" at 144,1134.23 h20
  text "FLOW_OUT3" at 27.8,903 h20
  text "FORCE_LOW1" at 233.53,808 h20
  text "FLOW_OUT1" at 238.5,702.79 h20
  text "PCB_Inductor1" at 1125,589 h20
  text "FLOW_OUT2" at 228,506.69 h20
  text "FORCE_LOW3" at 20.8,503 h20
  text "PCB_Inductor3" at 1451.06,411.81 h20
  text "FORCE_LOW2" at 229,404.59 h20
  text "FLOW_TRIG1" at 1661.39,248.45 h20
  text "PCB_Inductor2" at 1123.11,221.42 h20
  text "FLOW_TRIG2" at 1657.79,150 h20
  text "FLOW_TRIG3" at 81.8,71.93 h20
  text "TIDA-010050" at 568.7,51.76 h80
  text ".Layer_Name" at 449,-564.49 h20
Bottom Overlay:
  text ".Layer_Name" at 449,-564.49 h20
Top Paste:
  text ".Layer_Name" at 449,-564.49 h20
Bottom Paste:
  text ".Layer_Name" at 449,-564.49 h20
Top Solder:
  text ".Layer_Name" at 449,-564.49 h20
  text ".Layer_Name" at 449,-564.49 h20
Bottom Solder:
  text ".Layer_Name" at 449,-564.49 h20
Drill Guide:
  text ".Layer_Name" at 449,-564.49 h20
M1 Board Outline:
  the board outline again, w10
  text ".Layer_Name" at 449,-564.49 h20
M2 Board Dimensions:
  rectangle: 0,-275 125,-150
  rectangle: 125,-400 500,-275
  lines w7: 0,-275 1000,-275 ; 125,-400 125,-150 ; 250,-400 250,-150 ; 500,-400 500,-150 ; 750,-400 750,-150 ; 0,-400 1000,-400 1000,-150 0,-150 0,-400
  text ".Layer_Name" at 577,-858.49 h20
M3 3D STEP Top:
  text ".Layer_Name" at 577,-858.49 h20
M4 3D STEP Bottom:
  text ".Layer_Name" at 577,-858.49 h20
M5 Assembly Top:
  lines w10: -292,-930.17 6308,-930.17 ; -292,-726.83 6310,-726.83 ; -292,-523.5 -292,-1133.5 3713,-1133.5 6310,-1133.5 6310,-523.5 -291.5,-523.5 -291.5,-1133.5 1284,-1133.5 ; 2173,-1133.5 2173,-523.5 ; 3440,-726.83 3440,-523.5 ; 4280,-726.83 4280,-523.5 ; 4902,-1140 4902,-937.17
  text "COMPONENTS MARKED 'DNP' SHOULD NOT BE POPULATED." at 1153.5,-318.5 h20
  text "ASSEMBLY VARIANT:" at 1153,-434 h20
  text ".VariantName" at 2189,-434 h20
  text "PCB VIEWED FROM TOP SIDE" at -228.5,-655.67 h20
  text "BOARD #:" at 2248,-655.67 h20
  text ".PRJ_Number" at 2793.5,-655.67 h20
  text "REV:" at 3638,-655.67 h20
  text ".PCB_Rev" at 3929.5,-655.67 h20
  text "SVN REV:" at 4476,-655.67 h20
  text ".VersionControl_RevNumber" at 4982,-655.67 h20
  text "TID #:" at 2248,-859 h20
  text ".TID" at 2793.5,-859 h20
  text "PLOT NAME =" at -228.5,-1064.34 h20
  text ".plot_File_Name" at 577,-1064.34 h20
  text "GENERATED    :" at 2250,-1064.34 h20
  text ".Print_Date" at 3119.5,-1064.34 h20
  text ".Print_Time" at 3848.5,-1064.34 h20
  text "TEXAS INSTRUMENTS" at 5113,-1064.34 h20
M6 Assembly Bottom:
  lines w10: -292.5,-727.33 6309.5,-727.33 ; -290.5,-930.67 6309.5,-930.67 ; 1115.5,-1140.5 1115.5,-937.67 ; 1737.5,-727.33 1737.5,-524 ; 2577.5,-727.33 2577.5,-524 ; 3844.5,-1134 3844.5,-524 ; 4733.5,-1134 6309,-1134 6309,-524 -292.5,-524 -292.5,-1134 2304.5,-1134 6309.5,-1134 6309.5,-524
  text "COMPONENTS MARKED 'DNP' SHOULD NOT BE POPULATED." at 6102,-318 h20
  text ".VariantName" at 5058,-434 h20
  text "ASSEMBLY VARIANT:" at 6097,-434 h20
  text ".VersionControl_RevNumber" at 1035.5,-656.17 h20
  text "SVN REV:" at 1541.5,-656.17 h20
  text ".PCB_Rev" at 2088,-656.17 h20
  text "REV:" at 2379.5,-656.17 h20
  text ".PRJ_Number" at 3224,-656.17 h20
  text "BOARD #:" at 3769.5,-656.17 h20
  text "PCB VIEWED FROM BOTTOM SIDE" at 6246,-656.17 h20
  text ".TID" at 3224,-859.5 h20
  text "TID #:" at 3769.5,-859.5 h20
  text "TEXAS INSTRUMENTS" at 904.5,-1064.84 h20
  text ".Print_Time" at 2169,-1064.84 h20
  text ".Print_Date" at 2898,-1064.84 h20
  text "GENERATED    :" at 3767.5,-1064.84 h20
  text ".plot_File_Name" at 5440.5,-1064.84 h20
  text "PLOT NAME =" at 6246,-1064.84 h20
M9 Title Sheet:
  drawing of 57 lines, arcs and shapes, not listed
  text "1" at 739.84,8036.5 h20
  text "2" at 3235.5,8036.5 h20
  text "3" at 5724.84,8036.5 h20
  text "4" at 8231.51,8036.5 h20
  text "5" at 10730.5,8036.5 h20
  text "6" at 13235.5,8036.5 h20
  text "A" at -416.5,6893.5 h20
  text "A" at 14383.5,6893.5 h20
  text "B" at -416.5,4513.5 h20
  text "B" at 14383.5,4513.5 h20
  text "C" at -416.5,2138.5 h20
  text "C" at 14383.5,2138.5 h20
  text "PROJECT TITLE:" at 11343.5,277.5 h20
  text ".PRJ_Title" at 11393.5,144.17 h20
  text "DESIGNED FOR:" at 11343.5,-23.5 h20
  text ".PRJ_Customer" at 11393.5,-163.5 h20
  text "D" at -416.5,-231.5 h20
  text "D" at 14383.5,-231.5 h20
  text "FILE NAME:" at 11343.5,-323.5 h20
  text ".PCB_File_Name_No_Path" at 11393.5,-443.5 h20
  text "Texas Instruments (TI) and/or its licensors do not warrant the accuracy or completeness of this specification" at 6374,-605.34 h20
  text "ENGINEER:" at 11343.5,-613.5 h20
  text "LAYOUT BY:" at 12848.5,-613.5 h20
  text "or any information contained therein. TI and/or its licensors do not warrant that this design will meet" at 6329.01,-718 h20
  text ".PRJ_Engineer" at 11393.5,-768.49 h20
  text ".PCB_Layout" at 12899,-768.49 h20
  text "the specifications, will be suitable for your application or fit for any particular purpose, or will operate in" at 6329.01,-830.67 h20
  text ".Layer_Name" at 577,-858.49 h20
  text "ALTIUM DESIGNER VERSION:" at 12848.5,-923.5 h20
  text "an implementation. TI and/or its licensors do not warrant that the design is production worthy. You should" at 6329.01,-943.33 h20
  text "completely validate and test your design implementation to confirm the system functionality for your application." at 6374,-1056 h20
  text ".print_Scale" at 11393.5,-1056.83 h20
  text ".Application_BuildNumber" at 12899,-1056.83 h20
  text "1" at 739.84,-1263.5 h20
  text "2" at 3235.5,-1263.5 h20
  text "3" at 5724.84,-1263.5 h20
  text "4" at 8231.51,-1263.5 h20
  text "5" at 10730.5,-1263.5 h20
  text "6" at 13235.5,-1263.5 h20
M10 Fab Notes:
  drawing of 188 lines, arcs and shapes, not listed
  text "MIN. TRACK WIDTH:" at 11737.46,6224.05 h20
  text "8" at 12833.7,6224.05 h20
  text "MIL" at 12988.46,6224.05 h20
  text "MIN. CLEARANCE:" at 11737.46,6099.92 h20
  text "0.2" at 12773.7,6099.93 h20
  text "mm" at 12988.46,6099.92 h20
  text "MIN. VIA PAD SIZE:" at 11737.46,5975.8 h20
  text "24" at 12803.71,5975.8 h20
  text "MIL" at 12988.46,5975.8 h20
  text "0.05mm (2MIL)" at 12432.46,5845.9 h20
  text "MINIMUM ANNULAR RING" at 11408.23,5837.67 h20
  text "EXTERNAL" at 13140.46,5837.67 h20
  text "PER" at 11608.23,5727.55 h20
  text "IPC-D-275 CLASS 2 LEVEL C" at 11828.23,5727.54 h20
  text "MIL, HOLES" at 13316.46,5627.07 h20
  text "+/-" at 12924,5618.48 h20
  text "+/-" at 13778,5618.48 h20
  text "REGISTRATION TOLERANCES:" at 11408.23,5617.42 h20
  text "METAL" at 12608,5617.42 h20
  text "5" at 13184.2,5617.42 h20
  text "3" at 14017.2,5617.42 h20
  text "MIL" at 14133.46,5617.42 h20
  text "HOLE SIZE TOLERANCE (UNLESS OTHERWISE SPECIFIED):" at 11408.23,5519.1 h20
  text "+/-" at 13778,5516.23 h20
  text "3" at 14017.2,5515.17 h20
  text "MIL" at 14133.46,5515.17 h20
  text "MATERIAL:" at 11333.46,5377.52 h20
  text "FR-4 High Tg" at 12319.9,5249 h20
  text "X" at 12175.46,5241.01 h20
  text "FR-408" at 11754.46,5236.49 h20
  text "OTHER" at 13242.46,5236.49 h20
  text "62 MIL (1.6mm) +/-10%" at 12074.56,5093.46 h20
  text "X" at 11954.46,5091.01 h20
  text "THICKNESS:" at 11408.23,5085.24 h20
  text "OTHER" at 13359.46,5085.24 h20
  text "TOLERANCE:" at 11408.23,4946.92 h20
  text "X" at 12256.46,4946.92 h20
  text "ANSI IPC-6012 TYPE 3 CLASS 2" at 12434.48,4946.92 h20
  text "OTHER +/-" at 12434.46,4802.73 h20
  text "BOW & TWIST:" at 11408.23,4657.54 h20
  text "X" at 12256.46,4657.54 h20
  text "ANSI IPC-6012 TYPE 3 CLASS 2" at 12434.48,4657.54 h20
  text "OTHER +/-" at 12434.46,4510.85 h20
  text "DRILLING:" at 11333.46,4380.23 h20
  text "NC_DRILL FILES" at 13094.46,4275.04 h20
  text "REFERENCE:" at 11408.23,4271.1 h20
  text "X" at 12065.46,4271.01 h20
  text "AS SHOWN" at 12243.46,4271.1 h20
  text "X" at 12966.46,4271.1 h20
  text "OTHER" at 13392.46,4128.85 h20
  text "PTH COPPER THICKNESS:" at 11407.91,4125.32 h20
  text "X" at 12547.14,4125.32 h20
  text "20-30 um" at 12675.14,4125.32 h20
  text "BOARD FINISH:" at 11333.46,3977.73 h20
  text "SILKSCREEN:" at 11488.68,3867.6 h20
  text "X" at 12446.46,3867.6 h20
  text "TOP" at 12563.46,3867.6 h20
  text "X" at 12956.46,3867.6 h20
  text "BOTTOM" at 13074.46,3867.6 h20
  text "SILKSCREEN COLOR:" at 11488.68,3712.41 h20
  text "X" at 12445.46,3712.41 h20
  text "WHITE" at 12563.46,3712.41 h20
  text "OTHER" at 13074.46,3712.41 h20
  text "X" at 12576.46,3568.96 h20
  text "GREEN" at 12694.46,3568.96 h20
  text "OTHER" at 13312.46,3568.96 h20
  text "SOLDER RESIST COLOR:" at 11488.68,3562.1 h20
  text "X" at 12576.46,3414.71 h20
  text "MATTE" at 12694.46,3414.71 h20
  text "SEMI-GLOSS" at 13312,3414.07 h20
  text "IMMERSION GOLD (ENIG)" at 12394.46,3241.94 h20
  text "ENEPIG" at 13732,3234.72 h20
  text "SURFACE FINISH:" at 11333.46,3233.72 h20
  text "X" at 12216.46,3233.72 h20
  text "IMM. TIN/SILVER OR EQUIV" at 11663,3096.4 h20
  text "OTHER" at 13094.46,3092.47 h20
  text "ARRAY/PANEL:" at 11333.46,2937.09 h20
  text "CUT AND TRIM PER M1 BOARD OUTLINE" at 12394.46,2928.87 h20
  text "N.C. ROUTE" at 12394.46,2792.9 h20
  text "X" at 13082.46,2792.9 h20
  text "V. SCORE" at 13260.46,2792.9 h20
  text "CERTIFICATION:" at 11333.46,2663.77 h20
  text "MATERIALS AND WORKMANSHIP FOR ALL PCBS" at 12058.46,2663.77 h20
  text "TO MEET OR EXCEED THE REQUIREMENTS OF:" at 12058.46,2569.71 h20
  text "X" at 11695.97,2441.08 h20
  text "ANSI IPC-A-600F CLASS ->" at 11823.96,2441.08 h20
  text "X" at 13471.97,2441.08 h20
  text "2" at 13581.96,2441.08 h20
  text "1" at 13266.96,2439.58 h20
  text "3" at 13935.96,2439.58 h20
  text "X" at 12507.97,2293.39 h20
  text "RoHS" at 12635.96,2293.39 h20
  text "OTHER" at 13280.36,2293.39 h20
  text "PER ORDER" at 13677.42,2293.39 h20
  text "ALL BOARDS MUST MEET OR EXCEED UL94-V0 REQUIREMENTS." at 11361,2139.57 h20
  text "PCB MUST BEAR THE UL94V-0 UL REGISTERED MATERIAL ID NUMBER" at 11361,2023.5 h20
  text "ADDITIONAL REQUIREMENTS:" at 11333.46,1854.08 h20
  text "MICROSECTION:" at 11408.23,1746.95 h20
  text "YES" at 12313.96,1746.95 h20
  text "REQUIRED" at 13175.46,1602.62 h20
  text "BARE BOARD ELEC. TEST:" at 11408.23,1599.76 h20
  text "NONE" at 12713.96,1599.76 h20
  text "X" at 13057.46,1599.76 h20
  text "PER ORDER" at 13767.46,1599.76 h20
  text "XX MIL VIAS REQUIRE NON-CONDUCTIVE FILL AND PLANARIZE" at 11576.38,1394.82 h20
  text "XX MIL VIAS REQUIRE CONDUCTIVE FILL AND PLANARIZE" at 11584.38,1290.84 h20
  text "OUTER XX MIL TRACES REQUIRE 50 OHM SINGLE-ENDED IMPEDANCE" at 11583.39,1127.46 h20
  text "LAYER 2 & 3 (INNER LAYERS) XX MIL WIDE, XX MIL SPACE / TRACES REQUIRE 100 OHM DIFFERENTIAL IMPEDANCE" at 11575.39,891.74 h20
  text ".Layer_Name" at 577,-858.49 h20
M11 Gerber Information:
  lines w10: -292,-930.17 6308,-930.17 ; -292,-726.83 6310,-726.83 ; -292,-523.5 -292,-1133.5 3713,-1133.5 6310,-1133.5 6310,-523.5 -291.5,-523.5 -291.5,-1133.5 1284,-1133.5 ; 2173,-1133.5 2173,-523.5 ; 3440,-726.83 3440,-523.5 ; 4280,-726.83 4280,-523.5 ; 4902,-1140 4902,-937.17
  text "ALL ARTWORK VIEWED FROM TOP SIDE" at -228.5,-655.67 h20
  text "BOARD #:" at 2248,-655.67 h20
  text ".PRJ_Number" at 2793.5,-655.67 h20
  text "REV:" at 3638,-655.67 h20
  text ".PCB_Rev" at 3929.5,-655.67 h20
  text "SVN REV:" at 4476,-655.67 h20
  text ".VersionControl_RevNumber" at 4982,-655.67 h20
  text "LAYER NAME =" at -228.5,-858.49 h20
  text "TID #:" at 2248,-859 h20
  text ".TID" at 2793.5,-859 h20
  text "PLOT NAME =" at -228.5,-1064.34 h20
  text ".plot_File_Name" at 577,-1064.34 h20
  text "GENERATED    :" at 2250,-1064.34 h20
  text ".Print_Date" at 3119.5,-1064.34 h20
  text ".Print_Time" at 3848.5,-1064.34 h20
  text "TEXAS INSTRUMENTS" at 5113,-1064.34 h20
M12 Stackup:
  text ".Layer_Name" at 577,-858.49 h20
M13 Component Bodies Top:
  text ".Layer_Name" at 577,-858.49 h20
M14 Component Bodies Bottom:
  text ".Layer_Name" at 577,-858.49 h20
M15 Courtyards Top:
  text ".Layer_Name" at 577,-858.49 h20
M16 Courtyards Bottom:
  text ".Layer_Name" at 577,-858.49 h20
